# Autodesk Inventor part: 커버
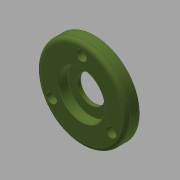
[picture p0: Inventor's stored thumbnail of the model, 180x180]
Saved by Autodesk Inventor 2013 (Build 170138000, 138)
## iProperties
Created: 2016-06
Part Number: 커버
Material: 알루미늄 6061
Document SubType Name: Modeling
Designer: mduedu
Density: 2.71 g/cm^3
Author: mduedu
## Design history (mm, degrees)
sketch "스케치1"
  geometry: C1 r 34 at (0, 0); 1 further point
  constraints: 1 centre point, 1 coincident
  dimensions: "d0" = 68 diameter of C1
extrude "돌출1" new body sketch "스케치1" distance "d2" = 10; taper "d3" = 0 deg
sketch "스케치2"
  geometry: C1 r 21 at (0, 0); 1 further point
  constraints: 1 centre point, 1 coincident
  dimensions: "d4" = 42 diameter of C1
extrude "돌출2" join sketch "스케치2" distance "d6" = 3; taper "d7" = 0 deg
fillet "모깎기1" dims "d8" = 3
hole "구멍1" diameter "d11" = 35; stored, may be unused: countersink angle "d15" = 90 deg, drill point angle "d17" = 0 deg; dims "d9" = 10, "d10" = 10, "d12" = 6, "d13" = 4, "d14" = 2, "d16" = 3
hole "구멍2" diameter "d20" = 35; stored, may be unused: countersink angle "d24" = 90 deg, drill point angle "d26" = 0 deg; dims "d21" = 6, "d22" = 4, "d23" = 2, "d25" = 7.3, "d73" = 10, "d74" = 10
hole "구멍3" diameter "d29" = 21; stored, may be unused: countersink angle "d33" = 90 deg, drill point angle "d35" = 0 deg; dims "d27" = 10, "d28" = 10, "d30" = 6, "d31" = 4, "d32" = 2, "d34" = 5
fillet "모깎기2" dims "d36" = 3
fillet "모깎기3" dims "d37" = 0.1
chamfer "모따기1" distance "d38" = 0.7; stored, may be unused: second distance "d39" = 2, angle "d40" = 30 deg
chamfer "모따기2" distance "d42" = 0.5; stored, may be unused: second distance "d43" = 2, angle "d44" = 30 deg
sketch "스케치5" dims "d60" = 52
  geometry: 3 further points
  constraints: 2 vertical alignment, 1 coincident, 2 other
hole "구멍5" sketch "스케치5" at (0, 26) diameter "d61" = 4.5; stored, may be unused: countersink angle "d65" = 90 deg, drill point angle "d67" = 118 deg; dims "d62" = 6, "d63" = 8, "d64" = 4.6, "d66" = 8
node "솔리드1"
pattern_circular "원형 패턴1" dims angle "d69" = 360 deg
